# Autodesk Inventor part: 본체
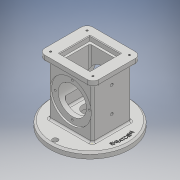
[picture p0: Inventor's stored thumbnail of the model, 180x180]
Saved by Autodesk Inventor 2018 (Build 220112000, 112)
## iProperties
Created: 2019-08
Part Number: 본체
Material: 일반
Document SubType Name: Modeling
Designer: USER
Density: 1 g/cm^3
Appearance: 기본값
Author: USER
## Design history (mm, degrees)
sketch "스케치2"
  geometry: L1 (0, 66)-(74, 66); L2 (74, 66)-(74, 0); L3 (74, 0)-(0, 0); L4 (0, 0)-(0, 66); 1 further point
  constraints: 8 end point, 2 parallel, 1 coincident, 1 horizontal, 1 perpendicular
  dimensions: "d2" = 74 distance of L1.start L1.end; "d3" = 66 distance of L1.end L2.end
extrude "돌출1" new body sketch "스케치2" distance "d4" = 88; taper "d5" = 0 deg
node "작업 평면1"
node "작업 평면2"
sketch "스케치3"
  geometry: 1 further point
sketch "스케치4"
  geometry: L1 (0, 66)-(74, 66) reference; L2 (74, 66)-(74, 0) reference; L3 (74, 0)-(0, 0) reference; L4 (0, 0)-(0, 66) reference; C1 r 67.5 at (37, 33); 3 further points
  constraints: 2 midpoint, 1 centre point, 1 horizontal alignment, 1 vertical alignment
  dimensions: "d8" = 135 diameter of C1
extrude "돌출2" join sketch "스케치4" distance "d9" = 10; taper "d10" = 0 deg
node "작업 평면3"
sketch "스케치5"
  geometry: L1 (-9, 74)-(83, 74); L2 (83, 74)-(83, -8); L3 (83, -8)-(-9, -8); L4 (-9, -8)-(-9, 74); L5 (74, 66)-(0, 66) reference; L6 (0, 66)-(0, 0) reference; L7 (0, 0)-(74, 0) reference; L8 (74, 0)-(74, 66) reference; 5 further points
  constraints: 8 end point, 4 midpoint, 2 parallel, 1 horizontal, 1 horizontal alignment, 1 perpendicular, 1 vertical alignment
  dimensions: "d12" = 92 distance of L1.start L1.end; "d13" = 82 distance of L1.end L2.end
extrude "돌출3" join sketch "스케치5" distance "d14" = 10; taper "d15" = 0 deg
sketch "스케치6"
  geometry: L1 (-9, 74)-(83, 74) reference; L2 (-9, -8)-(-9, 74) reference; L3 (83, -8)-(-9, -8) reference; L4 (83, 74)-(83, -8) reference; L5 (11, 59)-(63, 59); L6 (63, 59)-(63, 7); L7 (63, 7)-(11, 7); L8 (11, 7)-(11, 59); 5 further points
  constraints: 8 end point, 4 midpoint, 2 parallel, 1 horizontal, 1 horizontal alignment, 1 perpendicular, 1 vertical alignment
  dimensions: "d16" = 52 distance of L5.start L5.end; "d17" = 52 distance of L5.end L6.end
extrude "돌출4" cut sketch "스케치6" distance "d18" = 8; taper "d19" = 0 deg
sketch "스케치7"
  geometry: L1 (74, 0)-(0, 0) reference; L2 (74, 0)-(74, 88) reference; L3 (0, 88)-(74, 88) reference; L4 (0, 0)-(0, 88) reference; L5 (-30.5, -10)-(104.5, -10) reference; L6 (83, 88)-(-9, 88) reference; C1 r 35 at (37, 44); 2 further points
  constraints: 1 centre point, 1 midpoint, 1 vertical alignment
  dimensions: "d20" = 70 diameter of C1; "d21" = 54 distance from line of L5 C1.centre
extrude "돌출5" cut sketch "스케치7" distance "d22" = 3; taper "d23" = 0 deg
sketch "스케치8"
  geometry: C1 r 35 at (0, 0) reference; C2 r 24 at (0, 0); 1 further point
  constraints: 1 centre point, 1 coincident
  dimensions: "d24" = 48 diameter of C2
extrude "돌출6" cut sketch "스케치8" distance "d25" = 8; taper "d26" = 0 deg
sketch "스케치9"
  geometry: C1 r 67.5 at (0, 0) reference; C2 r 25 at (0, 0); 1 further point
  constraints: 1 centre point, 1 coincident
  dimensions: "d27" = 50 diameter of C2
extrude "돌출7" cut sketch "스케치9" distance "d28" = 18; taper "d29" = 0 deg
sketch "스케치10"
  geometry: C1 r 25 at (0, 0) reference; C2 r 12.5 at (0, 0); 1 further point
  constraints: 1 centre point, 1 coincident
  dimensions: "d30" = 25 diameter of C2
extrude "돌출8" cut sketch "스케치10" distance "d31" = 10; taper "d32" = 0 deg
node "작업 평면4"
sketch "스케치11"
  geometry: L1 (15, 11)-(59, 11); L2 (59, 11)-(59, 55); L3 (59, 55)-(15, 55); L4 (15, 55)-(15, 11); L5 (11, 59)-(63, 59) reference; L6 (11, 7)-(11, 59) reference; L7 (63, 7)-(11, 7) reference; L8 (63, 59)-(63, 7) reference; L9 (11, 59)-(63, 59) reference; L10 (11, 7)-(11, 59) reference; 5 further points
  constraints: 8 end point, 4 midpoint, 2 parallel, 1 horizontal, 1 horizontal alignment, 1 perpendicular, 1 vertical alignment
  dimensions: "d34" = 44 distance of L3.end L1.start; "d35" = 44 distance of L2.end L3.end
extrude "돌출9" cut sketch "스케치11" distance "d36" = 74; taper "d37" = 0 deg
sketch "스케치12"
  geometry: C1 r 25 at (0, 0) reference; C2 r 67.5 at (0, 0) reference; 4 further points
  constraints: 2 vertical alignment, 1 horizontal alignment
  dimensions: "d38" = 59 distance of C1.centre point (0, 59); "d39" = 59 distance of point (-59, 0) C1.centre; "d40" = 59 distance of C1.centre point (0, -59)
hole "구멍1" sketch "스케치12" at (-59, 0), (0, -59), (0, 59) diameter "d41" = 9; stored, may be unused: countersink angle "d45" = 90 deg, drill point angle "d47" = 118 deg; dims "d42" = 6, "d43" = 4, "d44" = 2, "d46" = 8
sketch "스케치13"
  geometry: L1 (11, 7)-(11, 59) reference; L2 (11, 59)-(63, 59) reference; L3 (63, 59)-(63, 7) reference; L4 (63, 7)-(11, 7) reference; L5 (-9, 74)-(83, 74) reference; L6 (-9, -8)-(-9, 74) reference; L7 (83, -8)-(-9, -8) reference; L8 (83, 74)-(83, -8) reference; 5 further points
  constraints: 2 horizontal alignment, 2 vertical alignment
  dimensions: "d48" = 10 distance from line of L6 point (1, 64); "d49" = 10 distance from line of L5 point (1, 64); "d53" = 10 distance from line of L7 point (73, 2); "d54" = 10 distance from line of L8 point (73, 2)
hole "구멍2" sketch "스케치13" at (1, 64), (73, 64), (73, 2), (1, 2) diameter "d55" = 3.242; stored, may be unused: countersink angle "d59" = 90 deg, drill point angle "d61" = 118 deg; dims "d56" = 4, "d57" = 4, "d58" = 2, "d60" = 6
sketch "스케치14"
  geometry: C1 r 24 at (0, 0) reference; C2 r 35 at (0, 0) reference; 2 further points
  constraints: 1 vertical alignment
  dimensions: "d62" = 29 distance of point (0, 29) C1.centre
hole "구멍3" sketch "스케치14" at (0, 29) diameter "d63" = 3.242; stored, may be unused: countersink angle "d67" = 90 deg, drill point angle "d69" = 118 deg; dims "d64" = 4, "d65" = 4, "d66" = 2, "d68" = 6
node "작업 평면5"
sketch "스케치15"
  geometry: L1 (0, 66)-(0, 0) reference; L2 (0, 66)-(-88, 66) reference; L3 (-88, 0)-(-88, 66) reference; L4 (0, 0)-(-88, 0) reference; L5 (10, -34.5)-(10, 100.5) reference; L6 (-88, 74)-(-88, -8) reference; 4 further points
  constraints: 2 horizontal alignment, 1 midpoint
  dimensions: "d74" = 37 distance from line of L5 point (-27, 33); "d75" = 43 distance of point (-27, 33) point (-70, 33)
hole "구멍4" sketch "스케치15" at (-70, 33), (-27, 33) diameter "d76" = 4.917; stored, may be unused: countersink angle "d80" = 90 deg, drill point angle "d82" = 118 deg; dims "d77" = 12, "d78" = 4, "d79" = 2, "d81" = 17.1
fillet "모깎기1" dims "d83" = 3
fillet "모깎기2" dims "d84" = 3
fillet "모깎기3" dims "d85" = 3
sketch "스케치17"
  geometry: L1 (22, -46)-(22, -9.592) reference; L2 (-22, -46)-(22, -46) reference; L3 (-22, -46)-(-22, -9.592) reference; A1 r 24 centre (0, 0) between (-22, -9.592) and (22, -9.592) reference; 2 further points
  constraints: 1 coincident
hole "구멍5" sketch "스케치17" at (0, 0) diameter "d86" = 48; stored, may be unused: countersink angle "d90" = 90 deg, drill point angle "d92" = 118 deg; dims "d87" = 12, "d88" = 4, "d89" = 2, "d91" = 17.1
fillet "모깎기4" dims "d93" = 3
fillet "모깎기5" dims "d94" = 3
chamfer "모따기1" distance "d95" = 3; stored, may be unused: second distance "d96" = 2, angle "d97" = 45 deg
chamfer "모따기2" distance "d98" = 1; stored, may be unused: second distance "d99" = 2, angle "d100" = 45 deg
fillet "모깎기6" dims "d101" = 10
fillet "모깎기7" dims "d102" = 3
fillet "모깎기8" dims "d103" = 3
node "작업 평면6"
sketch "스케치18"
  geometry: 1 further point
sketch "스케치19"
  geometry: C1 r 4.5 at (0, -59) reference; C2 r 4.5 at (-59, 0) reference; C3 r 4.5 at (0, 59) reference; C4 r 25 at (0, 0) reference; C5 r 67.5 at (0, 0) reference; 2 further points
  constraints: 1 coincident, 1 horizontal alignment, 2 other
feature "엠보싱1" sketch "스케치19" dims "d105" = 0.5, "d106" = 0
node "솔리드1"
mirror "미러1"
pattern_circular "원형 패턴1" dims angle "d71" = 360 deg
mirror "미러2"
node "투영된 루프1"
node "투영된 루프2"
node "투영된 루프3"
node "투영된 루프4"
node "투영된 루프5"
node "투영된 루프6"
node "투영된 루프7"
node "투영된 루프8"
node "투영된 루프9"
node "투영된 루프10"
node "투영된 루프11"
node "투영된 루프12"
node "투영된 루프14"
node "투영된 루프15"
other parameters: "d6" = 0, "d11" = 98, "d33" = 33, "d73" = 33, "d104" = 37
